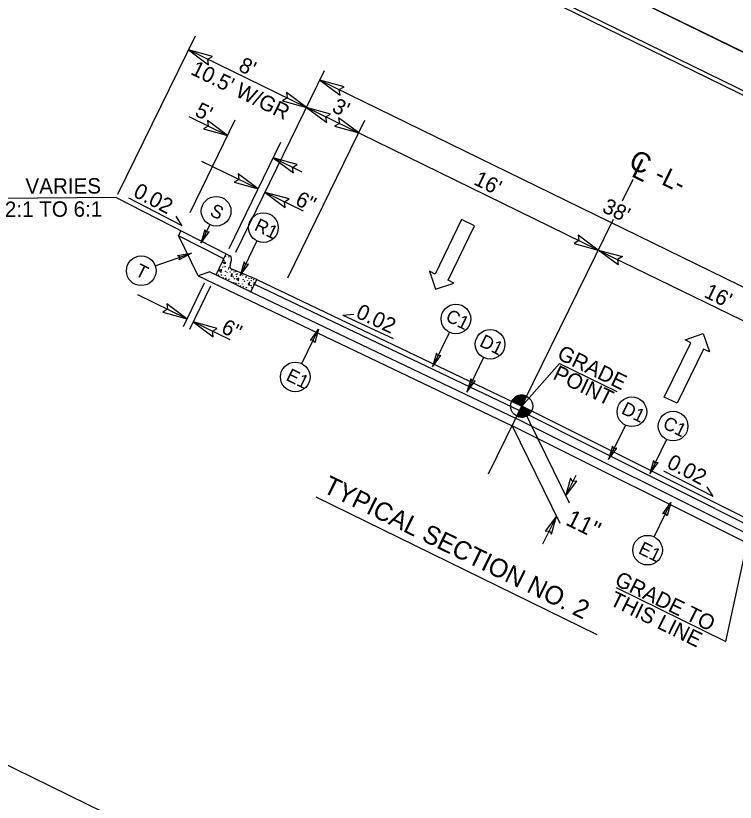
# Model space of a CAD drawing. Extents: x 1518247 to 1523638, y 635234 to 639927.
# Drawn here: x 1521243 to 1521708, y 638068 to 638577 of the extents above; entities that cross this region are included whole.
import ezdxf

# ---------------------------------------------------------------- set-up
doc = ezdxf.new("R2010")
doc.units = 0
for name, color, linetype in [('Default', 7, 'Continuous'), ('Prop Dimension', 7, 'Continuous'), ('Prop Dimension Text', 7, 'Continuous'), ('Prop Lane Arrow CELL', 7, 'Continuous'), ('Prop Shade Light', 7, 'Continuous'), ('Sheet Cutting Line CELL', 7, 'Continuous'), ('Sheet Plot Border Inside CELL', 7, 'Continuous'), ('Sheet Plot Border Outside CELL', 7, 'Continuous'), ('Sheet Typical CELL', 7, 'Continuous'), ('Typical Arrow Superelevation CELL', 7, 'Continuous'), ('Typical Berm CELL', 7, 'Continuous'), ('Typical Berm Information CELL', 7, 'Continuous'), ('Typical Curb CELL', 7, 'Continuous'), ('Typical Grade Point Symbol CELL', 7, 'Continuous'), ('Typical Hinge Slope Arterial CELL', 7, 'Continuous'), ('Typical Hinge Slope Interstate CELL', 7, 'Continuous'), ('Typical ID Circle CELL', 7, 'Continuous'), ('Typical Pavement Slope CELL', 7, 'Continuous'), ('Typical Pavement Slope Information CELL', 7, 'Continuous'), ('Typical Text Centerline CELL', 7, 'Continuous'), ('Typical Text General CELL', 7, 'Continuous'), ('Typical Text Grade Point CELL', 7, 'Continuous'), ('Typical Text ID Circle CELL', 7, 'Continuous'), ('Typical Text Label CELL', 7, 'Continuous')]:
    doc.layers.add(name, color=color, linetype=linetype)

# ---------------------------------------------------------------- blocks, each defined once
blk = doc.blocks.new('TERMINATOR')
at = {"layer": 'Prop Shade Light'}
blk.add_lwpolyline([(-0.469, 0.081), (0, 0), (-0.471, -0.083), (-0.411, 0)], close=True, dxfattribs=at)

msp = doc.modelspace()

# ---------------------------------------------------------------- linework, layer by layer
at = {"layer": 'Default'}
for points in [[(1522438.02, 638198.63), (1520925.25, 638938.49), (1521408.53, 639926.64), (1522921.3, 639186.78)], [(1520441.97, 637950.34), (1521954.73, 637210.48), (1522438.02, 638198.63), (1520925.25, 638938.49)]]:
    msp.add_lwpolyline(points, close=True, dxfattribs=at)
at = {"layer": 'Prop Dimension'}
for p, q in [((1521308.72, 638461.34), (1521358.8, 638563.73)), ((1521430.76, 638517.4), (1521354.4, 638554.74)), ((1521384.94, 638423.71), (1521442.42, 638541.23)), ((1521439.41, 638535.07), (1521816.69, 638350.55)), ((1521475.68, 638495.43), (1521430.76, 638517.4)), ((1521354.49, 638511.48), (1521379.69, 638499.15)), ((1521355.38, 638449.44), (1521384.65, 638509.28)), ((1521418.63, 638407.23), (1521468.48, 638509.17)), ((1521380.59, 638426.19), (1521414.16, 638494.84)), ((1521619.41, 638425.14), (1521475.68, 638495.43)), ((1521399.4, 638464.65), (1521363.06, 638482.43)), ((1521409.28, 638484.68), (1521427.63, 638475.71)), ((1521428.67, 638450.34), (1521403.89, 638462.46)), ((1521619.41, 638425.14), (1521763.14, 638354.84)), ((1521364.61, 638403.77), (1521350.83, 638375.53)), ((1521368.59, 638401.68), (1521354.92, 638373.66)), ((1521353.35, 638380.69), (1521321.58, 638396.2)), ((1521381.39, 638367), (1521357.39, 638378.72)), ((1521594.36, 638351.67), (1521569.9, 638324.1)), ((1521569.9, 638324.1), (1521600.49, 638261.53)), ((1521563.7, 638311.45), (1521594.51, 638248.42)), ((1521604.8, 638279.27), (1521598.26, 638265.92)), ((1521592.32, 638252.9), (1521583.43, 638234.75)), ((1521701.89, 638171.92), (1521715.64, 638235.41)), ((1521630.89, 638206.71), (1521701.89, 638171.92)), ((1521165.23, 638127.14), (1521679.14, 637875.79))]:
    msp.add_line(p, q, dxfattribs=at)
at = {"layer": 'Prop Lane Arrow CELL'}
for p, q in [((1521530.98, 638444.79), (1521514, 638409.6)), ((1521522.3, 638405.6), (1521539.28, 638440.79)), ((1521539.28, 638440.79), (1521530.98, 638444.79)), ((1521514, 638409.6), (1521510.23, 638411.42)), ((1521510.23, 638411.42), (1521514.21, 638399.74)), ((1521526.07, 638403.78), (1521522.3, 638405.6)), ((1521514.21, 638399.74), (1521526.07, 638403.78)), ((1521675.5, 638366.95), (1521687.14, 638371.04)), ((1521687.14, 638371.04), (1521691.29, 638359.21)), ((1521662.07, 638330.02), (1521679.26, 638365.11)), ((1521679.26, 638365.11), (1521675.5, 638366.95)), ((1521687.53, 638361.05), (1521670.34, 638325.96)), ((1521691.29, 638359.21), (1521687.53, 638361.05)), ((1521670.34, 638325.96), (1521662.07, 638330.02))]:
    msp.add_line(p, q, dxfattribs=at)
at = {"layer": 'Prop Shade Light'}
for points in [[(1521364.86, 638438.28), (1521362.34, 638429.64), (1521367.67, 638436.97), (1521365.76, 638436.64)], [(1521347.36, 638421.67), (1521356.24, 638423.18), (1521348.35, 638418.72), (1521348.89, 638420.59)], [(1521390.29, 638417.4), (1521387.77, 638408.75), (1521393.1, 638416.08), (1521391.19, 638415.75)], [(1521433.28, 638366.56), (1521438.56, 638373.86), (1521436.05, 638365.15), (1521435.13, 638366.86)], [(1521514.79, 638358.3), (1521512.27, 638349.65), (1521517.6, 638356.98), (1521515.68, 638356.65)], [(1521536.89, 638341.9), (1521534.37, 638333.26), (1521539.7, 638340.59), (1521537.79, 638340.26)], [(1521628.61, 638298.25), (1521626.09, 638289.6), (1521631.42, 638296.93), (1521629.5, 638296.61)], [(1521655.22, 638288.98), (1521652.7, 638280.34), (1521658.03, 638287.67), (1521656.11, 638287.34)], [(1521661.12, 638254.5), (1521666.4, 638261.8), (1521663.88, 638253.09), (1521662.97, 638254.8)]]:
    msp.add_lwpolyline(points, close=True, dxfattribs=at)
at = {"layer": 'Sheet Cutting Line CELL'}
for p, q in [((1520925.25, 638938.49), (1522438.02, 638198.63)), ((1522438.02, 638198.63), (1520925.25, 638938.49))]:
    msp.add_line(p, q, dxfattribs=at)
at = {"layer": 'Sheet Plot Border Inside CELL'}
msp.add_lwpolyline([(1522424.11, 638180.44), (1520927.06, 638912.61), (1520463.51, 637964.8), (1521960.55, 637232.62)], close=True, dxfattribs=at)
at = {"layer": 'Sheet Plot Border Outside CELL'}
for points in [[(1522921.3, 639186.78), (1521408.53, 639926.64), (1520925.25, 638938.49), (1522438.02, 638198.63)], [(1522438.02, 638198.63), (1520925.25, 638938.49), (1520441.97, 637950.34), (1521954.73, 637210.48)]]:
    msp.add_lwpolyline(points, close=True, dxfattribs=at)
at = {"layer": 'Sheet Typical CELL'}
msp.add_line((1521377.19, 638419.42), (1521347.84, 638434.35), dxfattribs=at)
msp.add_lwpolyline([(1522411.76, 638183.64), (1521064.29, 638842.66), (1520602.97, 637899.43), (1521950.45, 637240.41)], close=True, dxfattribs=at)
at = {"layer": 'Typical Arrow Superelevation CELL'}
msp.add_line((1521350.28, 638440.87), (1521346.33, 638447), dxfattribs=at)
at = {"layer": 'Typical Berm CELL'}
msp.add_line((1521307.66, 638459.17), (1521378.82, 638422.58), dxfattribs=at)
at = {"layer": 'Typical Berm Information CELL'}
msp.add_line((1521350.28, 638440.87), (1521315.74, 638458.63), dxfattribs=at)
at = {"layer": 'Typical Curb CELL'}
for p, q in [((1521372.23, 638409.1), (1521378.82, 638422.58)), ((1521378.82, 638422.58), (1521381.16, 638421.43)), ((1521377.59, 638416.1), (1521376.66, 638417.32)), ((1521376.66, 638417.32), (1521378.34, 638417.25)), ((1521378.34, 638417.25), (1521377.59, 638416.1)), ((1521381.66, 638417.01), (1521381.73, 638417.15)), ((1521375.69, 638412.47), (1521374.27, 638411.91)), ((1521374.27, 638411.91), (1521375.5, 638410.65)), ((1521375.5, 638410.65), (1521375.69, 638412.47)), ((1521398.53, 638405.98), (1521382.33, 638412.69)), ((1521372.23, 638409.1), (1521394.69, 638398.12)), ((1521382.72, 638409.97), (1521381.67, 638408.59)), ((1521381.67, 638408.59), (1521382.7, 638407.98)), ((1521382.7, 638407.98), (1521382.72, 638409.97)), ((1521386.91, 638406.99), (1521385.49, 638406.43)), ((1521385.49, 638406.43), (1521386.71, 638405.17)), ((1521386.71, 638405.17), (1521386.91, 638406.99)), ((1521394.69, 638398.12), (1521398.53, 638405.98)), ((1521393.94, 638404.49), (1521392.88, 638403.11)), ((1521392.88, 638403.11), (1521393.93, 638402.49)), ((1521393.93, 638402.49), (1521393.94, 638404.49))]:
    msp.add_line(p, q, dxfattribs=at)
for centre in [(1521378.22, 638421.03), (1521380.39, 638420.54), (1521377.48, 638418.35), (1521376.55, 638414.24), (1521377.96, 638414.39), (1521378.46, 638411.4), (1521379.4, 638410.46), (1521380.27, 638412.9), (1521380.45, 638413.65), (1521381.3, 638410.96), (1521382.23, 638412.21), (1521383.71, 638410.83), (1521384.94, 638411.13), (1521373.84, 638409.08), (1521375.64, 638408.87), (1521376.81, 638407.25), (1521378.08, 638408.53), (1521378.54, 638406.88), (1521380.54, 638406.28), (1521383.52, 638407.59), (1521384.09, 638406.55), (1521385.3, 638409.39), (1521385.54, 638408.22), (1521386.03, 638409.6), (1521387.77, 638408.75), (1521389.18, 638408.91), (1521389.68, 638405.91), (1521390.62, 638404.97), (1521391.5, 638407.41), (1521391.67, 638408.16), (1521392.52, 638405.48), (1521393.45, 638406.72), (1521394.93, 638405.34), (1521395.19, 638406.92), (1521396.36, 638406.06), (1521381.52, 638404.66), (1521383.56, 638404.04), (1521385.06, 638403.6), (1521386.86, 638403.38), (1521388.03, 638401.76), (1521389.3, 638403.05), (1521389.76, 638401.39), (1521391.76, 638400.8), (1521394.74, 638402.1), (1521395.31, 638401.06), (1521396.52, 638403.9), (1521396.76, 638402.74), (1521397.25, 638404.12), (1521392.74, 638399.17), (1521394.78, 638398.55)]:
    msp.add_ellipse(centre, major_axis=(0.053, 0.108), ratio=0.666667, dxfattribs=at)
for centre, major_axis, end_param in [((1521379.58, 638418.2), (1.58, 3.23), 6.283185), ((1521383.82, 638415.95), (-1.58, -3.23), 6.324802)]:
    msp.add_ellipse(centre, major_axis=major_axis, ratio=0.666667, start_param=4.712389, end_param=end_param, dxfattribs=at)
at = {"layer": 'Typical Grade Point Symbol CELL'}
for p, q in [((1521573.04, 638330.51), (1521569.9, 638324.1)), ((1521563.5, 638327.26), (1521569.9, 638324.1)), ((1521569.9, 638324.1), (1521563.5, 638327.26)), ((1521566.76, 638317.69), (1521569.9, 638324.1)), ((1521569.9, 638324.1), (1521576.31, 638320.96))]:
    msp.add_line(p, q, dxfattribs=at)
for points in [[(1521570.64, 638325.61), (1521564.42, 638328.66)], [(1521570.71, 638325.74), (1521564.51, 638328.78)], [(1521570.77, 638325.87), (1521564.61, 638328.88)], [(1521570.83, 638326), (1521564.71, 638329)], [(1521570.89, 638326.12), (1521564.81, 638329.1)], [(1521570.96, 638326.25), (1521564.92, 638329.21)], [(1521571.02, 638326.38), (1521565.02, 638329.32)], [(1521571.08, 638326.51), (1521565.14, 638329.42)], [(1521571.14, 638326.64), (1521565.26, 638329.52)], [(1521571.21, 638326.77), (1521565.38, 638329.62)], [(1521571.27, 638326.89), (1521565.5, 638329.72)], [(1521571.33, 638327.02), (1521565.62, 638329.82)], [(1521571.4, 638327.15), (1521565.76, 638329.91)], [(1521571.46, 638327.28), (1521565.89, 638330.01)], [(1521571.52, 638327.41), (1521566.02, 638330.1)], [(1521571.58, 638327.53), (1521566.17, 638330.19)], [(1521571.65, 638327.66), (1521566.32, 638330.27)], [(1521571.71, 638327.79), (1521566.47, 638330.36)], [(1521571.77, 638327.92), (1521566.62, 638330.45)], [(1521571.84, 638328.05), (1521566.78, 638330.53)], [(1521571.9, 638328.18), (1521566.94, 638330.6)], [(1521571.96, 638328.3), (1521567.12, 638330.68)], [(1521572.02, 638328.43), (1521567.29, 638330.75)], [(1521572.09, 638328.56), (1521567.47, 638330.82)], [(1521572.15, 638328.69), (1521567.66, 638330.89)], [(1521572.21, 638328.82), (1521567.87, 638330.95)], [(1521572.28, 638328.95), (1521568.07, 638331)], [(1521572.34, 638329.07), (1521568.29, 638331.06)], [(1521572.4, 638329.2), (1521568.51, 638331.11)], [(1521572.46, 638329.33), (1521568.75, 638331.15)], [(1521572.53, 638329.46), (1521568.99, 638331.19)], [(1521572.59, 638329.59), (1521569.26, 638331.22)], [(1521572.65, 638329.71), (1521569.55, 638331.24)], [(1521572.72, 638329.84), (1521569.85, 638331.25)], [(1521572.78, 638329.97), (1521570.19, 638331.24)], [(1521572.84, 638330.1), (1521570.55, 638331.22)], [(1521572.9, 638330.23), (1521571, 638331.16)], [(1521572.97, 638330.36), (1521571.51, 638331.07)], [(1521573.03, 638330.48), (1521572.33, 638330.83)], [(1521569.95, 638324.2), (1521563.54, 638327.34), (1521563.54, 638327.34)], [(1521570.01, 638324.33), (1521563.6, 638327.47)], [(1521570.08, 638324.46), (1521563.68, 638327.59)], [(1521570.14, 638324.59), (1521563.74, 638327.72)], [(1521570.2, 638324.71), (1521563.82, 638327.84)], [(1521570.27, 638324.84), (1521563.9, 638327.96)], [(1521570.33, 638324.97), (1521563.98, 638328.08)], [(1521570.39, 638325.1), (1521564.07, 638328.2)], [(1521570.45, 638325.23), (1521564.14, 638328.32)], [(1521570.52, 638325.35), (1521564.23, 638328.43)], [(1521570.58, 638325.48), (1521564.33, 638328.55)], [(1521576.01, 638320.4), (1521569.62, 638323.53)], [(1521576.08, 638320.53), (1521569.69, 638323.66)], [(1521576.15, 638320.65), (1521569.75, 638323.79)], [(1521576.22, 638320.77), (1521569.81, 638323.92)], [(1521576.29, 638320.9), (1521576.29, 638320.9), (1521569.87, 638324.04)], [(1521570.34, 638316.98), (1521567.17, 638318.53)], [(1521570.61, 638317), (1521567.24, 638318.66)], [(1521570.87, 638317.04), (1521567.3, 638318.79)], [(1521571.12, 638317.07), (1521567.36, 638318.92)], [(1521571.36, 638317.12), (1521567.42, 638319.04)], [(1521571.58, 638317.17), (1521567.49, 638319.17)], [(1521571.8, 638317.22), (1521567.55, 638319.3)], [(1521572, 638317.28), (1521567.61, 638319.43)], [(1521572.19, 638317.34), (1521567.68, 638319.56)], [(1521572.38, 638317.41), (1521567.74, 638319.69)], [(1521572.56, 638317.48), (1521567.8, 638319.81)], [(1521572.74, 638317.55), (1521567.86, 638319.94)], [(1521572.91, 638317.63), (1521567.93, 638320.07)], [(1521573.08, 638317.71), (1521567.99, 638320.2)], [(1521573.22, 638317.79), (1521568.05, 638320.33)], [(1521573.39, 638317.87), (1521568.12, 638320.45)], [(1521573.54, 638317.96), (1521568.18, 638320.58)], [(1521573.68, 638318.04), (1521568.24, 638320.71)], [(1521573.82, 638318.14), (1521568.3, 638320.84)], [(1521573.95, 638318.23), (1521568.37, 638320.97)], [(1521574.09, 638318.32), (1521568.43, 638321.1)], [(1521574.22, 638318.42), (1521568.49, 638321.22)], [(1521574.34, 638318.52), (1521568.56, 638321.35)], [(1521574.46, 638318.62), (1521568.62, 638321.48)], [(1521574.58, 638318.72), (1521568.68, 638321.61)], [(1521574.7, 638318.82), (1521568.74, 638321.74)], [(1521574.82, 638318.92), (1521568.81, 638321.86)], [(1521574.92, 638319.03), (1521568.87, 638321.99)], [(1521575.03, 638319.13), (1521568.93, 638322.12)], [(1521575.14, 638319.24), (1521569, 638322.25)], [(1521575.23, 638319.36), (1521569.06, 638322.38)], [(1521575.33, 638319.46), (1521569.12, 638322.51)], [(1521575.42, 638319.58), (1521569.18, 638322.63)], [(1521575.51, 638319.69), (1521569.25, 638322.76)], [(1521575.61, 638319.8), (1521569.31, 638322.89)], [(1521575.7, 638319.92), (1521569.37, 638323.02)], [(1521575.77, 638320.04), (1521569.43, 638323.15)], [(1521575.85, 638320.16), (1521569.5, 638323.28)], [(1521575.93, 638320.28), (1521569.56, 638323.4)], [(1521567.71, 638317.31), (1521566.8, 638317.76)], [(1521568.43, 638317.12), (1521566.86, 638317.89)], [(1521568.93, 638317.03), (1521566.92, 638318.02)], [(1521569.35, 638316.99), (1521566.98, 638318.15)], [(1521569.71, 638316.97), (1521567.05, 638318.27)], [(1521570.05, 638316.97), (1521567.11, 638318.4)]]:
    msp.add_lwpolyline(points, dxfattribs=at)
msp.add_circle((1521569.91, 638324.11), 7.14, dxfattribs=at)
for start, end in [(63.8867, 153.8867), (243.8867, 333.8867)]:
    msp.add_arc((1521569.91, 638324.11), 7.14, start, end, dxfattribs=at)
at = {"layer": 'Typical Hinge Slope Interstate CELL'}
for p, q in [((1521307.66, 638459.17), (1521231.44, 638458.45)), ((1521349.46, 638437.67), (1521347.84, 638434.35))]:
    msp.add_line(p, q, dxfattribs=at)
at = {"layer": 'Typical ID Circle CELL'}
for p, q in [((1521368.18, 638441.6), (1521362.34, 638429.64)), ((1521398.64, 638431.02), (1521387.77, 638408.75)), ((1521332.87, 638414.94), (1521356.24, 638423.18)), ((1521427.66, 638351.61), (1521438.56, 638373.86)), ((1521523.14, 638371.91), (1521512.27, 638349.65)), ((1521545.24, 638355.52), (1521534.37, 638333.26)), ((1521636.96, 638311.87), (1521626.09, 638289.6)), ((1521663.57, 638302.6), (1521652.7, 638280.34)), ((1521655.49, 638239.55), (1521666.4, 638261.8))]:
    msp.add_line(p, q, dxfattribs=at)
for centre in [(1521372.26, 638450.24), (1521402.84, 638439.63), (1521323.83, 638411.75), (1521527.34, 638380.53), (1521549.44, 638364.13), (1521423.44, 638343), (1521641.16, 638320.48), (1521667.77, 638311.21), (1521651.28, 638230.94)]:
    msp.add_circle(centre, 9.59, dxfattribs=at)
at = {"layer": 'Typical Pavement Slope CELL'}
for p, q in [((1521360.54, 638408.49), (1521347.9, 638434.48)), ((1521368.15, 638411.11), (1521360.54, 638408.49)), ((1521368.15, 638411.11), (1521372.23, 638409.1)), ((1521360.54, 638408.49), (1521563.7, 638311.45)), ((1521398.53, 638405.98), (1521570.05, 638324.03)), ((1521397.07, 638402.99), (1521568.53, 638321.29)), ((1521394.69, 638398.12), (1521566.38, 638316.09)), ((1521739.89, 638239.03), (1521569.9, 638324.1)), ((1521738.32, 638235.81), (1521568.53, 638321.29)), ((1521736.05, 638231.17), (1521565.89, 638316.33)), ((1521765.2, 638210.57), (1521563.7, 638311.45))]:
    msp.add_line(p, q, dxfattribs=at)
at = {"layer": 'Typical Pavement Slope Information CELL'}
for p, q in [((1521454.14, 638383.08), (1521461.41, 638383.74)), ((1521454.14, 638383.08), (1521486.8, 638367.94)), ((1521693.78, 638265.72), (1521661.88, 638282.15)), ((1521693.78, 638265.72), (1521689.83, 638271.86))]:
    msp.add_line(p, q, dxfattribs=at)
at = {"layer": 'Typical Text Centerline CELL'}
for p, q in [((1521635.03, 638457.02), (1521641.9, 638471.04)), ((1521548.41, 638280.24), (1521629.14, 638445.01))]:
    msp.add_line(p, q, dxfattribs=at)
at = {"layer": 'Typical Text Grade Point CELL'}
msp.add_line((1521594.36, 638351.67), (1521631.31, 638333.57), dxfattribs=at)
at = {"layer": 'Typical Text Label CELL'}
msp.add_line((1521436.67, 638265.49), (1521618.57, 638176.37), dxfattribs=at)

# ---------------------------------------------------------------- block references
at = {"layer": 'Prop Dimension'}
for p, xscale, yscale, rotation in [((1521354.4, 638554.74), 33.82820784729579, -36.41552511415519, 153.97926941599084), ((1521439.41, 638535.07), 33.82820784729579, -36.41552511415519, 153.97926941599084), ((1521430.76, 638517.4), 33.82820784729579, -36.41552511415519, -26.020730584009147), ((1521430.76, 638517.4), 33.82820784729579, -36.41552511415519, 153.97926941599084), ((1521379.69, 638499.15), 33.82820784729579, -36.41552511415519, -26.020730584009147), ((1521464.45, 638500.92), 33.82820784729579, -36.41552511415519, -26.020730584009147), ((1521409.21, 638484.72), 33.82820784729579, -36.41552511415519, 153.97926941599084), ((1521399.4, 638464.65), 33.82820784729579, -36.41552511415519, -26.020730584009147), ((1521403.89, 638462.46), 33.82820784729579, -36.41552511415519, 153.97926941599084), ((1521619.41, 638425.14), 33.82820784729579, -36.41552511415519, -26.020730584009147), ((1521619.41, 638425.14), 33.82820784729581, 36.4155251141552, 153.89617982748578), ((1521619.41, 638425.14), 33.82820784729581, 36.415525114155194, 153.89617982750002), ((1521353.35, 638380.69), 33.82820784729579, -36.41552511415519, -26.020730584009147), ((1521357.39, 638378.72), 33.82820784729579, -36.41552511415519, 153.97926941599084), ((1521598.26, 638265.92), 25.371155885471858, -27.31164383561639, -116.10382017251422), ((1521592.32, 638252.9), 25.371155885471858, -27.31164383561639, 63.89617982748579)]:
    msp.add_blockref('TERMINATOR', p, dxfattribs=dict(at, xscale=xscale, yscale=yscale, rotation=rotation))

# ---------------------------------------------------------------- texts
for s, height, rotation, p in [("8'", 9.969, 333.9793, (1521386, 638541.48)), ("10.5' W/GR", 9.969, 333.8962, (1521355.14, 638539.15)), ("3'", 9.969, 333.9793, (1521446.53, 638514.99)), ("5'", 9.969, 333.9793, (1521357.83, 638512.3)), ("16'", 9.969, 333.9793, (1521538.19, 638467.86)), ('6"', 9.969, 333.9793, (1521422.75, 638454.72)), ("38'", 9.969, 333.9793, (1521621.24, 638450.14)), ("16'", 9.969, 333.8962, (1521687.16, 638395.02)), ('6"', 9.969, 333.9793, (1521374.81, 638372.04)), ('11"', 11.189, 333.7115, (1521597.64, 638247.67))]:
    msp.add_text(s, height=height, rotation=rotation, dxfattribs=at).set_placement(p)
at = {"layer": 'Prop Dimension Text'}
for s, height, rotation, p in [('-L-', 11.962, 333.9793, (1521654.83, 638470.28)), ('TYPICAL SECTION NO. 2', 11.9625, 333.8962, (1521440.63, 638268.83))]:
    msp.add_text(s, height=height, rotation=rotation, dxfattribs=at).set_placement(p)
at = {"layer": 'Typical Berm Information CELL'}
msp.add_text('0.02', height=9.969, rotation=332.1708, dxfattribs=at).set_placement((1521317.94, 638460.19))
at = {"layer": 'Typical Hinge Slope Arterial CELL'}
for s, p in [('VARIES', (1521248.93, 638461.52)), ('2:1 TO 6:1', (1521235.62, 638446.52))]:
    msp.add_text(s, height=9.969, rotation=0.2071, dxfattribs=at).set_placement(p)
at = {"layer": 'Typical Pavement Slope Information CELL'}
for rotation, p in [(335.125, (1521461.96, 638381.71)), (332.7504, (1521663.04, 638284.64))]:
    msp.add_text('0.02', height=9.969, rotation=rotation, dxfattribs=at).set_placement(p)
at = {"layer": 'Typical Text Centerline CELL'}
for s, height, rotation, p in [('C', 13.08, 333.8962, (1521638.17, 638479.01)), ('L', 13.09, 333.8431, (1521640.11, 638473.08))]:
    msp.add_text(s, height=height, rotation=rotation, dxfattribs=at).set_placement(p)
at = {"layer": 'Typical Text General CELL'}
for s, p in [('GRADE TO', (1521629.29, 638208.78)), ('THIS LINE', (1521626.14, 638195.77))]:
    msp.add_text(s, height=9.969, rotation=333.8962, dxfattribs=at).set_placement(p)
at = {"layer": 'Typical Text Grade Point CELL'}
for s, p in [('GRADE', (1521592.08, 638355.08)), ('POINT', (1521589.38, 638342.04))]:
    msp.add_text(s, height=9.969, rotation=333.8962, dxfattribs=at).set_placement(p)
at = {"layer": 'Typical Text ID Circle CELL'}
for s, height, rotation, p in [('S', 8.58, 333.9793, (1521367.53, 638447.8)), ('R1', 8.581, 333.9793, (1521396.31, 638438.31)), ('T', 8.58, 333.9793, (1521319.28, 638408.95)), ('C1', 8.581, 333.9793, (1521520.01, 638379.6)), ('D1', 8.581, 333.9793, (1521542.01, 638363.26)), ('E1', 8.581, 333.8962, (1521416.83, 638341.2)), ('D1', 8.581, 333.9793, (1521633.72, 638319.61)), ('C1', 8.581, 333.9793, (1521660.44, 638310.28)), ('E1', 8.581, 333.8962, (1521644.67, 638229.14))]:
    msp.add_text(s, height=height, rotation=rotation, dxfattribs=at).set_placement(p)

doc.saveas('drawing.dxf')
